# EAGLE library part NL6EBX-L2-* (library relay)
6PDT FLATPACK 2AMP DIL RELAY NAiS 2 coil latching Source: http://www.mew-europe.com/.. en_ds_61014_0003.pdf
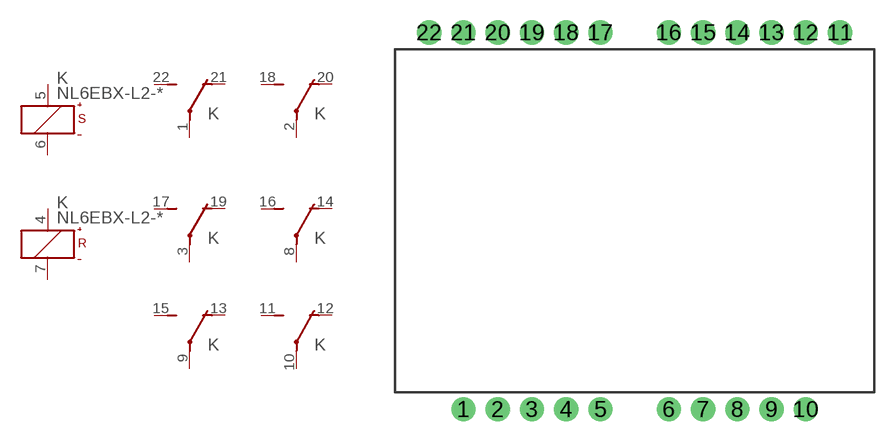
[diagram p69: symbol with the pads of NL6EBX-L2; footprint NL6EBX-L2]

Designator prefix K; gates S=K+-S R=K+-R 1=U 2=U 3=U 4=U 5=U 6=U

## NL6EBX-L2-DC5V (OC_FARNELL: unknown; OC_NEWARK: unknown), NL6EBX-L2-DC6V (OC_FARNELL: unknown; OC_NEWARK: unknown), NL6EBX-L2-DC12V (OC_FARNELL: unknown; OC_NEWARK: unknown), NL6EBX-L2-DC24V (OC_FARNELL: unknown; OC_NEWARK: unknown), NL6EBX-L2-DC48V (OC_FARNELL: unknown; OC_NEWARK: unknown), NL6EBX-L2-DC60V (OC_FARNELL: unknown; OC_NEWARK: unknown), NL6EBX-L2-DC110V (OC_FARNELL: unknown; OC_NEWARK: unknown)  [NL6EBX-L2]
1  1:P  pas
2  2:P  pas
3  3:P  pas
4  R:+  pas
5  S:+  pas
6  S:-  pas
7  R:-  pas
8  4:P  pas
9  5:P  pas
10  6:P  pas
11  6:S  pas
12  6:O  pas
13  5:O  pas
14  4:O  pas
15  5:S  pas
16  4:S  pas
17  3:S  pas
18  2:S  pas
19  3:O  pas
20  2:O  pas
21  1:O  pas
22  1:S  pas

## Footprint NL6EBX-L2 (pad centres in mm)
6PDT FLATPACK 2AMP DIL RELAY NAiS 2 coil latching Source: http://www.mew-europe.com/.. en_ds_61014_0003.pdf
drill 1.2 round: 1 -12.7,-13.97; 2 -10.16,-13.97; 3 -7.62,-13.97; 4 -5.08,-13.97; 5 -2.54,-13.97; 6 2.54,-13.97; 7 5.08,-13.97; 8 7.62,-13.97; 9 10.16,-13.97; 10 12.7,-13.97; 11 15.24,13.97; 12 12.7,13.97; 13 10.16,13.97; 14 7.62,13.97; 15 5.08,13.97; 16 2.54,13.97; 17 -2.54,13.97; 18 -5.08,13.97; 19 -7.62,13.97; 20 -10.16,13.97; 21 -12.7,13.97; 22 -15.24,13.97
